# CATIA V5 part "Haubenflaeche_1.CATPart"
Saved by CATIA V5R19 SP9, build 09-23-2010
Part number: Leuchte_lang.SLDPRT
Bounding box of the stored display mesh (mm): x 0 to 62, y -12.244 to 12.244, z 0 to 19.484
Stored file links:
  D:\tmp\Haubenflaeche.CATPart
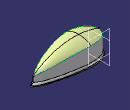
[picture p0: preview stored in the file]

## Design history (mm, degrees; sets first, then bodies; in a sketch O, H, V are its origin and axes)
Set1
  DatumSurface1 "Join"
  DatumCurve1
  DatumCurve2
  Plane1: type Offset, RefPlane yz-plane, Offset 18.5
  Sketch1 "Skizze.1" on Plane1, origin (18.5, 0, 0), H (0, 1, 0), V (0, 0, 1)
    intersected arc E1 centre (10117.2437, -346.7624) radius 10134.8307 from (-11.0962, 15.8997) to (-11.5484, 3.0421) ccw from face of DatumSurface1
    intersected arc E2 centre (-10117.2437, -346.7624) radius 10134.8307 from (11.5484, 3.0421) to (11.0962, 15.8997) ccw from face of DatumSurface1
    axis line L1 (0, 0) -> (0, 19.3)
    point P5 (0, 19.3)
    arc A1 centre (0, -0.5052) radius 19.8052 from (-11.0962, 15.8997) to (11.0962, 15.8997) cw
    length L1 = 19.3
    vertical: L1 V
    coincidence: A1 P5
  Sketch2 on zx-plane, origin (0, 0, 0), H (-1, 0, 0), V (0, 0, 1)
    reference intersected point E2 (-18.5, 19.3) from Sketch1.A1
    arc A1 centre (-23.28, -42.1413) radius 61.6269 from (-60.0716, 7.2981) to (-0.7, 15.2) cw
    coincidence: A1 E2
  Boundary1 "Begrenzung.1_geschlossen": Boundary edge of DatumSurface1
  Boundary2: Boundary edge of DatumSurface1
  Boundary3: Boundary edge of DatumSurface1
Set2
  Extrude1: Lim1 20, Lim2 0, Element1 Sketch2
  Extrude2: Lim1 20, Lim2 0, Element1 Sketch1
  Split1: ToCut Sketch2, Cutting Sketch1
  Split2: ToCut Sketch1, Cutting Split1
  Fill1: Boundary ({fillboundary BoundaryWire Split1, Support Extrude1}; Boundary3; {fillboundary BoundaryWire Split2, Support Extrude2})
  Fill2: Boundary ({fillboundary BoundaryWire Split1, Support Fill1}; Boundary2; {fillboundary BoundaryWire {split ToCut Sketch1, Cutting Split1}, Support Extrude2})
  Fill3: Boundary ({fillboundary BoundaryWire Split2, Support Fill1}; {fillboundary BoundaryWire {split ToCut Sketch2, Cutting Sketch1}, Support Extrude1}; Boundary3)
  Fill4: Boundary ({fillboundary BoundaryWire {split ToCut Sketch1, Cutting Split1}, Support Fill2}; {fillboundary BoundaryWire {split ToCut Sketch2, Cutting Sketch1}, Support Fill3}; Boundary2)
  Join1: Elements (Fill1; Fill2; Fill3; Fill4)
Body1 (main body)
